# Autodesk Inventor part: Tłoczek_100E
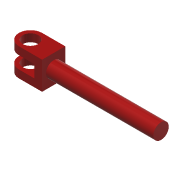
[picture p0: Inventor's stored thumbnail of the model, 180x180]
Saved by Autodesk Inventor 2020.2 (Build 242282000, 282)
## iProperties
Created: 2005-10
Part Number: Tłoczek_100E
Document SubType Name: Modeling
Designer: F.Stasiak
Density: 1 g/cm^3
Material: Ogólny
Appearance: Gładkie — czerwone
Manager: www.cadconsulting.pl
Company: Fabian Stasiak CAD Consulting
Author: F.Stasiak
Subject: Zbiór ćwiczeń. Autodesk Inventor 2020. Kurs podstawowy
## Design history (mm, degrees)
sketch "Szkic1"
  geometry: L1 (78.834, -0.5)-(93.834, -0.5); L2 (93.834, -0.5)-(93.834, -15.5); L3 (93.834, -15.5)-(78.834, -15.5); C1 r 5 at (78.834, -8) reference; A1 r 7.5 centre (78.834, -8) between (78.834, -0.5) and (78.834, -15.5)
  constraints: 6 end point, 2 point on circle, 2 tangent, 1 centre point, 1 coincident, 1 horizontal, 1 perpendicular
  dimensions: "d0" = 15 diameter of A1; "d1" = 15 distance of L1.end L2.end; "d2" = 15 distance from line of L2 C1.centre
extrude "Wyciągnięcie proste1" new body sketch "Szkic1" stored distance "d3" = 18; taper "d4" = 0 deg
sketch "Szkic2"
  geometry: L1 (78.834, -0.5)-(88.834, -0.5); L2 (88.834, -0.5)-(88.834, -15.5); L3 (88.834, -15.5)-(78.834, -15.5); C1 r 5 at (78.834, -8) reference; A1 r 7.5 centre (78.834, -8) between (78.834, -0.5) and (78.834, -15.5)
  constraints: 6 end point, 2 point on circle, 2 tangent, 1 centre point, 1 coincident, 1 horizontal, 1 perpendicular
  dimensions: "d5" = 15 diameter of A1; "d6" = 15 distance of L1.end L2.end; "d12" = 10 distance of L1.start L1.end
extrude "Wyciągnięcie proste2" cut sketch "Szkic2" stored distance "d7" = 8; taper "d8" = 0 deg
sketch "Szkic3"
  geometry: L1 (0, 15)-(0, 0) reference; L2 (18, 0)-(0, 0) reference; L3 (18, 0)-(18, 15) reference; L4 (18, 15)-(0, 15) reference; L5 (0, 15)-(18, 0); C1 r 5 at (9, 7.5)
  constraints: 2 end point, 1 centre point, 1 midpoint
  dimensions: "d9" = 10 diameter of C1
extrude "Wyciągnięcie proste3" join sketch "Szkic3" distance "d10" = 69.5; taper "d11" = 0 deg
node "Bryła1"
node "Korpusy bryłowe"
node "Korpusy powierzchniowe"
node "Odniesienie1"
node "Pętla rzutowana1"
